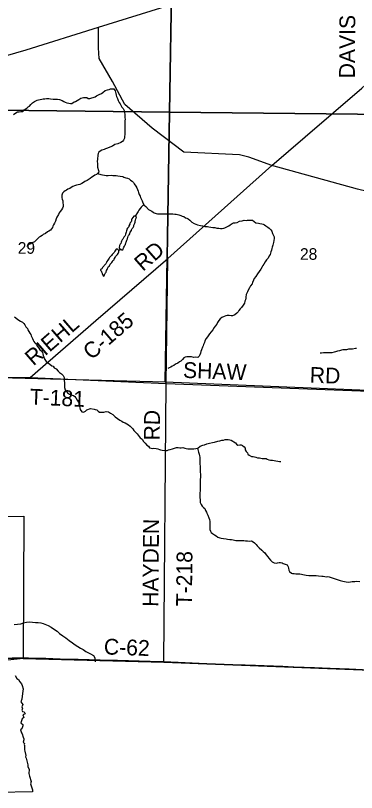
# Model space of a CAD drawing. Extents: x 1588073 to 2013523, y 1090242 to 1357120.
# Drawn here: x 1819023 to 1825493, y 1184242 to 1198993 of the extents above; entities that cross this region are included whole.
import ezdxf

# ---------------------------------------------------------------- set-up
doc = ezdxf.new("R2010")
doc.units = 0
for name, color, linetype in [('GM_X_Adjacent_County', 7, 'Continuous'), ('GM_X_Corporation', 7, 'Continuous'), ('GM_X_County', 7, 'Continuous'), ('GM_X_County_Road', 7, 'Continuous'), ('GM_X_County_Road_Text', 7, 'Continuous'), ('GM_X_Minor_Lake', 7, 'Continuous'), ('GM_X_Minor_River', 7, 'Continuous'), ('GM_X_Section', 7, 'Continuous'), ('GM_X_Section_Text', 7, 'Continuous'), ('GM_X_Township', 7, 'Continuous'), ('GM_X_Township_Road', 7, 'Continuous'), ('GM_X_Township_Road_Text', 7, 'Continuous')]:
    doc.layers.add(name, color=color, linetype=linetype)

msp = doc.modelspace()

# ---------------------------------------------------------------- linework, layer by layer
at = {"layer": 'GM_X_Adjacent_County'}
msp.add_lwpolyline([(1808199, 1186945), (1810942, 1186950), (1813328, 1186914), (1815460, 1186869), (1816005, 1186857), (1816631, 1186848), (1817077, 1186838), (1817700, 1186826), (1818180, 1186810), (1818871, 1186791), (1819168, 1186784), (1821835, 1186718), (1827562, 1186497), (1829633, 1186472), (1832499, 1186486), (1836614, 1186490), (1837772, 1186480), (1843068, 1186456), (1845738, 1186419), (1848393, 1186378), (1851014, 1186349), (1853645, 1186324), (1853690, 1186324), (1859011, 1186262)], dxfattribs=at)
at = {"layer": 'GM_X_Corporation'}
for points in [[(1816696, 1189462), (1819180, 1189491), (1819168, 1186784), (1818877, 1186753)], [(1819017, 1186466), (1819049, 1186409), (1819081, 1186387), (1819101, 1186344), (1819135, 1186307), (1819146, 1186275), (1819165, 1186211), (1819156, 1186120), (1819143, 1186014), (1819126, 1185966), (1819161, 1185912), (1819145, 1185869), (1819153, 1185832), (1819144, 1185806), (1819156, 1185780), (1819187, 1185774), (1819208, 1185736), (1819159, 1185716), (1819179, 1185665), (1819148, 1185642), (1819125, 1185566), (1819130, 1185559), (1819161, 1185533), (1819163, 1185508), (1819143, 1185453), (1819119, 1185431), (1819134, 1185377), (1819151, 1185355), (1819170, 1185291), (1819182, 1185260), (1819182, 1185240), (1819166, 1185198), (1819192, 1185173), (1819186, 1185151), (1819194, 1185136), (1819193, 1185052), (1819202, 1185027), (1819217, 1184946), (1819212, 1184916), (1819224, 1184891), (1819255, 1184767), (1819255, 1184738), (1819284, 1184681), (1819277, 1184603), (1819290, 1184554), (1819320, 1184448), (1819309, 1184408), (1819343, 1184291), (1819345, 1184254), (1818673, 1184242)]]:
    msp.add_lwpolyline(points, dxfattribs=at)
at = {"layer": 'GM_X_County'}
msp.add_lwpolyline([(1859011, 1186262), (1853690, 1186324), (1853645, 1186324), (1851014, 1186349), (1848393, 1186378), (1845738, 1186419), (1843068, 1186456), (1837772, 1186480), (1836614, 1186490), (1832499, 1186486), (1829633, 1186472), (1827562, 1186497), (1821835, 1186718), (1819168, 1186784), (1818871, 1186791), (1818180, 1186810), (1817700, 1186826), (1817077, 1186838), (1816631, 1186848), (1816005, 1186857), (1815460, 1186869), (1813328, 1186914), (1810942, 1186950), (1808199, 1186945)], dxfattribs=at)
at = {"layer": 'GM_X_County_Road'}
for points in [[(1816603, 1198446), (1818072, 1198310), (1818832, 1198227), (1819223, 1198343), (1820597, 1198772), (1821965, 1199198), (1823341, 1199611), (1823868, 1199755), (1824618, 1199777), (1825943, 1199752), (1827244, 1199779)], [(1819300, 1192124), (1820546, 1193205), (1821912, 1194383), (1823886, 1196148), (1824518, 1196688), (1825592, 1197615), (1825927, 1197911)], [(1816531, 1192135), (1819300, 1192124)], [(1818964, 1186803), (1819151, 1186798), (1819269, 1186796), (1819571, 1186790), (1819600, 1186789), (1819869, 1186782), (1820211, 1186773), (1820421, 1186766), (1820549, 1186762), (1820631, 1186761), (1820959, 1186754), (1821575, 1186737), (1821756, 1186730), (1821835, 1186727), (1822110, 1186715), (1822507, 1186697), (1822749, 1186686), (1823146, 1186671), (1823274, 1186668), (1823379, 1186664), (1823576, 1186657), (1823743, 1186651), (1824093, 1186638), (1824304, 1186630), (1824697, 1186615), (1824996, 1186603), (1825357, 1186589), (1825606, 1186579)]]:
    msp.add_lwpolyline(points, dxfattribs=at)
at = {"layer": 'GM_X_Minor_Lake'}
for points in [[(1821268, 1195186), (1821231, 1195133), (1821224, 1195115), (1821222, 1195097), (1821216, 1195077), (1821201, 1195059), (1821193, 1195043), (1821191, 1195029), (1821174, 1195002), (1821170, 1194984), (1821145, 1194954), (1821135, 1194936), (1821132, 1194922), (1821128, 1194906), (1821123, 1194878), (1821119, 1194859), (1821109, 1194841), (1821104, 1194819), (1821094, 1194803), (1821078, 1194787), (1821069, 1194771), (1821061, 1194748), (1821049, 1194734), (1821036, 1194710), (1821026, 1194690), (1821021, 1194668), (1821007, 1194654), (1820998, 1194627), (1820994, 1194609), (1820990, 1194595), (1820991, 1194577), (1821005, 1194560), (1821009, 1194559)], [(1821009, 1194559), (1821019, 1194556), (1821035, 1194546), (1821057, 1194547), (1821067, 1194565), (1821069, 1194579), (1821076, 1194593), (1821090, 1194613), (1821100, 1194631), (1821107, 1194648), (1821117, 1194676), (1821122, 1194692), (1821128, 1194710), (1821132, 1194730), (1821145, 1194752), (1821147, 1194766), (1821155, 1194780), (1821160, 1194802), (1821168, 1194816), (1821180, 1194831), (1821189, 1194849), (1821195, 1194863), (1821198, 1194883), (1821222, 1194909), (1821226, 1194924), (1821237, 1194952), (1821253, 1194972), (1821266, 1194994), (1821270, 1195012), (1821281, 1195038), (1821287, 1195051), (1821291, 1195071), (1821296, 1195095), (1821298, 1195109), (1821305, 1195133), (1821313, 1195149), (1821317, 1195165), (1821304, 1195177), (1821286, 1195186), (1821268, 1195186)], [(1820933, 1194556), (1820918, 1194536), (1820908, 1194518), (1820892, 1194497), (1820881, 1194483), (1820855, 1194455), (1820843, 1194439), (1820834, 1194426), (1820820, 1194414), (1820808, 1194398), (1820801, 1194384), (1820789, 1194370), (1820773, 1194347), (1820758, 1194325), (1820750, 1194307), (1820735, 1194281), (1820719, 1194262), (1820705, 1194248), (1820698, 1194234), (1820686, 1194220), (1820672, 1194208), (1820661, 1194187), (1820633, 1194173), (1820637, 1194159), (1820645, 1194145), (1820654, 1194125), (1820664, 1194104), (1820669, 1194090), (1820673, 1194076), (1820685, 1194058), (1820688, 1194044), (1820705, 1194052), (1820709, 1194068), (1820715, 1194083), (1820730, 1194105), (1820740, 1194119), (1820749, 1194151), (1820759, 1194173), (1820765, 1194191), (1820790, 1194226), (1820804, 1194244), (1820821, 1194270), (1820837, 1194291), (1820852, 1194307), (1820860, 1194321), (1820872, 1194343), (1820887, 1194352), (1820897, 1194366), (1820914, 1194400), (1820922, 1194420), (1820957, 1194459), (1820969, 1194473), (1820977, 1194489), (1820982, 1194507), (1820980, 1194532)], [(1820980, 1194532), (1820971, 1194547), (1820957, 1194555), (1820933, 1194556)]]:
    msp.add_lwpolyline(points, dxfattribs=at)
at = {"layer": 'GM_X_Minor_River'}
for points in [[(1818987, 1197116), (1819026, 1197148), (1819058, 1197163), (1819094, 1197167), (1819126, 1197173), (1819162, 1197174), (1819186, 1197200), (1819237, 1197237), (1819263, 1197257), (1819287, 1197275), (1819316, 1197305), (1819346, 1197335), (1819380, 1197360), (1819407, 1197374), (1819431, 1197386), (1819459, 1197391), (1819519, 1197403), (1819547, 1197409), (1819579, 1197412), (1819613, 1197416), (1819653, 1197417), (1819689, 1197413), (1819739, 1197408), (1819782, 1197406), (1819818, 1197406), (1819858, 1197397), (1819907, 1197377), (1819941, 1197364), (1819967, 1197348), (1819999, 1197338), (1820033, 1197331), (1820065, 1197323), (1820093, 1197322), (1820137, 1197352), (1820162, 1197364), (1820194, 1197378), (1820224, 1197401), (1820260, 1197423), (1820286, 1197431), (1820315, 1197434), (1820343, 1197438), (1820375, 1197436), (1820401, 1197421), (1820433, 1197421), (1820471, 1197433), (1820497, 1197440), (1820533, 1197452), (1820557, 1197466), (1820587, 1197482), (1820612, 1197493), (1820654, 1197515), (1820680, 1197535), (1820725, 1197568), (1820769, 1197580), (1820801, 1197592), (1820825, 1197599), (1820889, 1197599), (1820915, 1197566), (1820919, 1197538), (1820926, 1197514), (1820932, 1197482), (1820940, 1197458), (1820957, 1197417), (1820971, 1197381), (1820990, 1197343), (1821006, 1197319), (1821018, 1197289), (1821038, 1197256), (1821063, 1197226)], [(1821063, 1197226), (1821083, 1197188), (1821092, 1197149), (1821098, 1197119), (1821098, 1197079), (1821099, 1197051), (1821101, 1197025), (1821099, 1196995), (1821094, 1196963), (1821094, 1196935), (1821096, 1196911), (1821097, 1196879), (1821099, 1196853), (1821098, 1196793), (1821098, 1196769), (1821096, 1196732), (1821093, 1196694), (1821091, 1196668), (1821074, 1196630), (1821050, 1196601), (1821024, 1196585), (1820964, 1196560), (1820907, 1196546), (1820863, 1196514), (1820811, 1196491), (1820768, 1196473), (1820732, 1196462), (1820706, 1196448), (1820662, 1196436), (1820631, 1196421), (1820601, 1196397), (1820593, 1196373), (1820583, 1196341), (1820576, 1196267), (1820575, 1196225), (1820577, 1196185), (1820576, 1196151), (1820580, 1196117), (1820599, 1196048), (1820603, 1196024), (1820585, 1195998), (1820558, 1195975), (1820530, 1195961), (1820500, 1195945), (1820468, 1195923), (1820437, 1195902), (1820385, 1195860), (1820339, 1195845), (1820312, 1195825), (1820282, 1195805), (1820240, 1195788), (1820214, 1195782), (1820182, 1195774), (1820143, 1195761), (1820111, 1195747), (1820079, 1195729), (1820055, 1195709), (1820018, 1195696), (1819990, 1195680), (1819966, 1195668), (1819938, 1195648), (1819911, 1195623), (1819903, 1195585), (1819899, 1195561), (1819904, 1195531), (1819906, 1195505), (1819918, 1195474), (1819921, 1195438), (1819927, 1195400), (1819927, 1195368), (1819914, 1195338), (1819894, 1195304), (1819871, 1195270), (1819851, 1195247), (1819835, 1195213), (1819808, 1195163), (1819794, 1195133), (1819779, 1195087), (1819763, 1195053), (1819742, 1195017), (1819728, 1194993), (1819722, 1194969), (1819689, 1194920), (1819655, 1194900), (1819631, 1194888), (1819594, 1194856), (1819550, 1194835), (1819526, 1194819), (1819499, 1194795), (1819471, 1194786), (1819435, 1194748), (1819410, 1194724), (1819382, 1194698), (1819338, 1194675), (1819312, 1194661), (1819275, 1194647), (1819251, 1194628), (1819237, 1194604)], [(1820578, 1195992), (1820644, 1195972), (1820670, 1195969), (1820708, 1195961), (1820742, 1195957), (1820778, 1195958), (1820839, 1195962), (1820869, 1195959), (1820901, 1195955), (1820935, 1195956), (1820967, 1195950), (1821009, 1195946), (1821057, 1195935), (1821081, 1195927), (1821118, 1195914), (1821150, 1195908), (1821182, 1195896), (1821206, 1195867), (1821236, 1195847), (1821262, 1195821), (1821273, 1195797), (1821303, 1195756), (1821325, 1195722), (1821338, 1195690), (1821348, 1195661), (1821356, 1195631), (1821371, 1195593), (1821387, 1195563), (1821397, 1195537), (1821408, 1195510), (1821426, 1195472), (1821437, 1195440), (1821463, 1195394), (1821497, 1195367), (1821546, 1195309), (1821570, 1195296), (1821608, 1195276), (1821632, 1195260), (1821656, 1195249), (1821691, 1195235), (1821719, 1195231), (1821794, 1195230), (1821850, 1195231), (1821880, 1195231), (1821984, 1195230), (1822008, 1195227), (1822044, 1195223), (1822070, 1195219), (1822120, 1195210), (1822158, 1195196), (1822188, 1195187), (1822214, 1195177), (1822247, 1195155), (1822275, 1195146), (1822299, 1195134), (1822329, 1195110), (1822371, 1195071), (1822412, 1195045), (1822474, 1195018), (1822534, 1195005), (1822568, 1194999), (1822618, 1194988), (1822642, 1194986), (1822666, 1194986), (1822694, 1194984), (1822730, 1194977), (1822770, 1194971), (1822802, 1194966), (1822844, 1194958), (1822878, 1194956), (1822914, 1194951), (1822946, 1194951), (1822974, 1194956), (1822998, 1194962), (1823035, 1194984), (1823069, 1195000), (1823097, 1195019), (1823131, 1195043), (1823162, 1195055), (1823192, 1195060), (1823228, 1195066), (1823276, 1195086), (1823324, 1195095), (1823364, 1195105), (1823404, 1195104), (1823428, 1195106), (1823455, 1195108), (1823483, 1195107), (1823523, 1195105), (1823586, 1195060), (1823636, 1195048), (1823662, 1195043), (1823698, 1195037), (1823722, 1195029), (1823746, 1195018), (1823774, 1195002), (1823808, 1194978), (1823839, 1194957), (1823871, 1194925), (1823885, 1194897), (1823902, 1194856)], [(1821455, 1195408), (1821404, 1195352), (1821388, 1195328), (1821364, 1195298), (1821351, 1195273), (1821296, 1195181)], [(1823902, 1194856), (1823918, 1194818), (1823928, 1194790), (1823929, 1194758), (1823925, 1194722), (1823918, 1194682), (1823906, 1194636), (1823895, 1194594), (1823889, 1194568), (1823883, 1194540), (1823870, 1194506), (1823864, 1194480), (1823854, 1194456), (1823835, 1194430), (1823815, 1194386), (1823786, 1194358), (1823762, 1194319), (1823735, 1194275), (1823719, 1194247), (1823705, 1194223), (1823678, 1194179), (1823648, 1194131), (1823615, 1194088), (1823583, 1194040), (1823554, 1194000), (1823536, 1193966), (1823517, 1193926), (1823513, 1193898), (1823484, 1193863), (1823466, 1193825), (1823437, 1193777), (1823423, 1193747), (1823413, 1193723), (1823402, 1193695), (1823396, 1193649), (1823394, 1193625), (1823387, 1193595), (1823377, 1193571), (1823366, 1193533), (1823340, 1193497), (1823311, 1193452), (1823283, 1193426), (1823263, 1193396), (1823246, 1193368), (1823222, 1193340), (1823182, 1193311), (1823139, 1193293), (1823115, 1193289), (1823077, 1193296), (1823037, 1193298), (1823011, 1193292), (1822983, 1193279), (1822935, 1193259), (1822904, 1193233), (1822880, 1193202), (1822856, 1193164), (1822841, 1193136), (1822813, 1193094), (1822790, 1193068), (1822768, 1193028), (1822737, 1192989), (1822701, 1192947), (1822666, 1192895), (1822640, 1192863), (1822617, 1192818), (1822607, 1192788), (1822591, 1192750), (1822582, 1192720), (1822572, 1192696), (1822549, 1192646), (1822539, 1192612), (1822531, 1192586), (1822518, 1192552), (1822506, 1192526), (1822480, 1192502), (1822434, 1192505), (1822409, 1192503), (1822362, 1192514), (1822333, 1192514), (1822273, 1192511), (1822241, 1192505), (1822217, 1192493), (1822191, 1192465), (1822162, 1192434), (1822132, 1192416), (1822100, 1192394), (1822057, 1192371), (1822025, 1192349), (1821997, 1192333), (1821969, 1192319), (1821940, 1192302), (1821914, 1192290)], [(1821009, 1194559), (1820996, 1194536), (1820980, 1194532)], [(1819001, 1193271), (1819031, 1193253), (1819069, 1193224), (1819115, 1193192), (1819153, 1193173), (1819178, 1193145), (1819198, 1193121), (1819220, 1193085), (1819247, 1193050), (1819259, 1193024), (1819275, 1192996), (1819292, 1192964), (1819310, 1192937), (1819322, 1192913)], [(1819322, 1192913), (1819330, 1192889), (1819345, 1192859), (1819355, 1192831), (1819373, 1192804), (1819392, 1192780), (1819414, 1192756), (1819438, 1192709), (1819463, 1192677), (1819485, 1192647), (1819515, 1192626), (1819533, 1192598), (1819538, 1192570), (1819550, 1192540), (1819560, 1192512), (1819569, 1192482), (1819593, 1192441), (1819609, 1192413), (1819650, 1192392), (1819676, 1192376), (1819712, 1192344), (1819736, 1192335), (1819756, 1192307), (1819791, 1192283), (1819829, 1192244), (1819859, 1192216), (1819896, 1192191), (1819928, 1192159), (1819944, 1192121), (1819945, 1192063), (1819949, 1192018), (1819950, 1191976), (1819954, 1191934), (1819967, 1191888), (1819989, 1191854), (1820010, 1191829), (1820046, 1191805), (1820096, 1191784), (1820120, 1191778), (1820146, 1191760), (1820168, 1191733), (1820195, 1191689), (1820215, 1191655), (1820228, 1191627), (1820234, 1191602), (1820238, 1191570), (1820244, 1191546), (1820249, 1191516), (1820279, 1191472), (1820313, 1191465), (1820353, 1191483), (1820377, 1191505), (1820448, 1191532), (1820512, 1191521), (1820536, 1191515), (1820566, 1191505), (1820593, 1191482), (1820617, 1191462), (1820675, 1191461), (1820699, 1191463), (1820743, 1191477), (1820789, 1191472), (1820825, 1191444), (1820871, 1191417), (1820912, 1191371), (1820956, 1191340), (1821004, 1191310), (1821040, 1191291), (1821068, 1191271), (1821105, 1191258), (1821137, 1191242), (1821169, 1191224), (1821197, 1191199), (1821221, 1191173), (1821246, 1191149), (1821270, 1191114), (1821306, 1191076), (1821329, 1191054), (1821351, 1191027), (1821391, 1190977), (1821426, 1190948), (1821452, 1190904), (1821486, 1190873), (1821515, 1190835), (1821543, 1190815), (1821565, 1190786), (1821597, 1190778), (1821623, 1190772), (1821649, 1190776), (1821691, 1190773), (1821723, 1190769), (1821753, 1190756), (1821777, 1190748), (1821807, 1190740), (1821865, 1190735), (1821899, 1190735), (1821923, 1190747), (1821957, 1190754), (1822003, 1190766), (1822039, 1190779), (1822080, 1190791)], [(1825496, 1192673), (1825472, 1192669), (1825415, 1192661), (1825379, 1192658), (1825341, 1192656), (1825303, 1192649), (1825261, 1192645), (1825235, 1192643), (1825209, 1192638), (1825173, 1192626), (1825135, 1192618), (1825098, 1192607), (1825072, 1192605), (1825028, 1192591), (1824988, 1192590), (1824964, 1192590), (1824934, 1192588), (1824910, 1192591), (1824870, 1192589), (1824830, 1192581), (1824804, 1192580)], [(1822080, 1190791), (1822110, 1190791), (1822140, 1190788), (1822168, 1190788), (1822198, 1190790), (1822234, 1190779), (1822258, 1190773), (1822292, 1190767), (1822316, 1190764), (1822344, 1190764), (1822404, 1190767), (1822446, 1190771), (1822480, 1190779), (1822526, 1190818), (1822579, 1190836), (1822607, 1190841), (1822651, 1190859), (1822681, 1190865), (1822705, 1190874), (1822758, 1190886), (1822800, 1190895), (1822864, 1190911), (1822898, 1190920), (1822936, 1190928), (1822970, 1190934), (1823001, 1190941), (1823037, 1190945), (1823061, 1190945), (1823091, 1190940), (1823117, 1190930), (1823144, 1190912), (1823168, 1190898), (1823200, 1190883), (1823218, 1190855), (1823244, 1190839), (1823278, 1190840), (1823304, 1190842), (1823330, 1190830), (1823361, 1190803), (1823379, 1190777), (1823383, 1190747), (1823400, 1190713), (1823424, 1190692), (1823434, 1190666), (1823458, 1190646), (1823502, 1190623), (1823530, 1190619), (1823584, 1190606), (1823613, 1190598), (1823650, 1190596), (1823677, 1190591), (1823705, 1190583), (1823735, 1190581), (1823778, 1190580), (1823801, 1190572), (1823831, 1190560), (1823859, 1190553), (1823899, 1190549), (1823963, 1190540), (1824003, 1190532), (1824031, 1190529), (1824057, 1190525)], [(1822473, 1190777), (1822493, 1190706), (1822507, 1190666), (1822514, 1190636), (1822518, 1190610), (1822522, 1190574), (1822521, 1190492), (1822524, 1190419), (1822525, 1190353), (1822529, 1190321), (1822530, 1190283), (1822532, 1190237), (1822529, 1190181), (1822527, 1190143), (1822526, 1190081), (1822524, 1190035), (1822522, 1189868), (1822523, 1189838), (1822525, 1189806), (1822529, 1189774), (1822528, 1189750), (1822544, 1189710), (1822566, 1189675), (1822593, 1189655), (1822613, 1189631), (1822629, 1189598), (1822646, 1189566), (1822656, 1189542), (1822674, 1189506), (1822689, 1189458), (1822701, 1189425), (1822708, 1189387), (1822710, 1189351), (1822709, 1189271), (1822711, 1189237), (1822720, 1189205), (1822736, 1189176), (1822762, 1189162), (1822800, 1189132), (1822832, 1189113), (1822859, 1189091), (1822901, 1189074), (1822927, 1189068), (1822967, 1189062), (1823019, 1189057), (1823043, 1189051), (1823089, 1189046), (1823121, 1189042), (1823151, 1189038), (1823179, 1189031), (1823205, 1189029), (1823229, 1189025), (1823261, 1189026), (1823319, 1189026), (1823357, 1189023), (1823385, 1189021), (1823427, 1189017), (1823463, 1189016), (1823501, 1189020), (1823533, 1188999), (1823559, 1188983), (1823587, 1188953), (1823610, 1188922), (1823646, 1188886), (1823696, 1188841), (1823721, 1188819), (1823753, 1188789), (1823781, 1188754), (1823812, 1188714), (1823832, 1188690), (1823860, 1188653), (1823891, 1188619), (1823929, 1188600), (1823973, 1188598), (1823997, 1188604), (1824027, 1188611), (1824052, 1188611), (1824081, 1188603), (1824105, 1188592), (1824143, 1188578), (1824179, 1188562), (1824199, 1188527), (1824202, 1188499), (1824210, 1188463), (1824222, 1188435), (1824258, 1188408), (1824281, 1188400), (1824313, 1188398), (1824343, 1188394), (1824379, 1188391), (1824418, 1188391), (1824452, 1188386), (1824475, 1188380), (1824507, 1188376), (1824541, 1188369), (1824591, 1188361), (1824730, 1188359), (1824770, 1188355), (1824834, 1188350), (1824860, 1188346), (1824890, 1188342)], [(1824890, 1188342), (1824920, 1188339), (1824948, 1188341), (1824972, 1188339), (1825016, 1188326), (1825067, 1188306), (1825091, 1188297), (1825147, 1188281), (1825183, 1188266), (1825209, 1188258), (1825237, 1188252), (1825267, 1188245), (1825295, 1188239), (1825347, 1188236), (1825381, 1188242), (1825413, 1188246), (1825459, 1188247), (1825489, 1188251), (1825558, 1188250)], [(1818997, 1187429), (1819059, 1187438), (1819123, 1187445), (1819174, 1187461), (1819232, 1187474), (1819288, 1187482), (1819344, 1187477), (1819404, 1187472), (1819452, 1187470), (1819502, 1187461), (1819548, 1187449), (1819644, 1187412), (1819701, 1187383), (1819765, 1187338), (1819811, 1187304), (1819858, 1187261), (1819918, 1187216), (1819978, 1187180), (1820043, 1187129), (1820103, 1187082), (1820152, 1187047), (1820206, 1187013)], [(1820206, 1187013), (1820256, 1186984), (1820305, 1186954), (1820355, 1186917), (1820447, 1186872), (1820500, 1186845), (1820530, 1186797), (1820537, 1186720)]]:
    msp.add_lwpolyline(points, dxfattribs=at)
at = {"layer": 'GM_X_Section'}
for points in [[(1822034, 1202453), (1821947, 1197160), (1816597, 1197222), (1816749, 1202487)], [(1827365, 1202462), (1827296, 1197101), (1821947, 1197160), (1822034, 1202453)], [(1821947, 1197160), (1821865, 1192030), (1816539, 1192169), (1816597, 1197222)], [(1827296, 1197101), (1827255, 1191810), (1821865, 1192030), (1821947, 1197160)]]:
    msp.add_lwpolyline(points, close=True, dxfattribs=at)
at = {"layer": 'GM_X_Township'}
msp.add_lwpolyline([(1827562, 1186497), (1821835, 1186718), (1819168, 1186784), (1818871, 1186791), (1818180, 1186810), (1817700, 1186826), (1817077, 1186838), (1816631, 1186848), (1816005, 1186857), (1815460, 1186869), (1813328, 1186914), (1810942, 1186950), (1811129, 1192202), (1811473, 1199649)], dxfattribs=at)
at = {"layer": 'GM_X_Township_Road'}
for points in [[(1827537, 1193971), (1827537, 1193971), (1826724, 1194962), (1826215, 1195491), (1826145, 1195528), (1826060, 1195554), (1826032, 1195562), (1826004, 1195577), (1825906, 1195600), (1825513, 1195699), (1823886, 1196148), (1823448, 1196306), (1823272, 1196347), (1822215, 1196402), (1821615, 1196857), (1821095, 1197302), (1820861, 1197739), (1820612, 1198179), (1820599, 1198383), (1820597, 1198772)], [(1821884, 1192006), (1821912, 1194383)], [(1819300, 1192124), (1821884, 1192006), (1829598, 1191716)], [(1821835, 1186727), (1821884, 1192006)]]:
    msp.add_lwpolyline(points, dxfattribs=at)

# ---------------------------------------------------------------- texts
at = {"layer": 'GM_X_County_Road_Text'}
for s, rotation, p in [('RD', 41.14, (1821440, 1194124)), ('RIEHL', 40.8551, (1819363, 1192329)), ('C-185', 40.7203, (1820464, 1192442)), ('C-62', 357.9065, (1820695, 1186864))]:
    msp.add_text(s, height=300, rotation=rotation, dxfattribs=at).set_placement(p)
at = {"layer": 'GM_X_Section_Text'}
for s, p in [('29', (1819064, 1194470)), ('28', (1824421, 1194355))]:
    msp.add_text(s, height=221, rotation=0, dxfattribs=at).set_placement(p)
at = {"layer": 'GM_X_Township_Road_Text'}
for s, rotation, p in [('DAVIS', 89.5493, (1825462, 1197800)), ('SHAW', 357.8965, (1822197, 1192115)), ('RD', 358.0252, (1824603, 1192022)), ('T-181', 357.4736, (1819287, 1191608)), ('RD', 89.5063, (1821759, 1190924)), ('HAYDEN', 89.512, (1821732, 1187765)), ('T-218', 89.4386, (1822370, 1187776))]:
    msp.add_text(s, height=300, rotation=rotation, dxfattribs=at).set_placement(p)

doc.saveas('drawing.dxf')
